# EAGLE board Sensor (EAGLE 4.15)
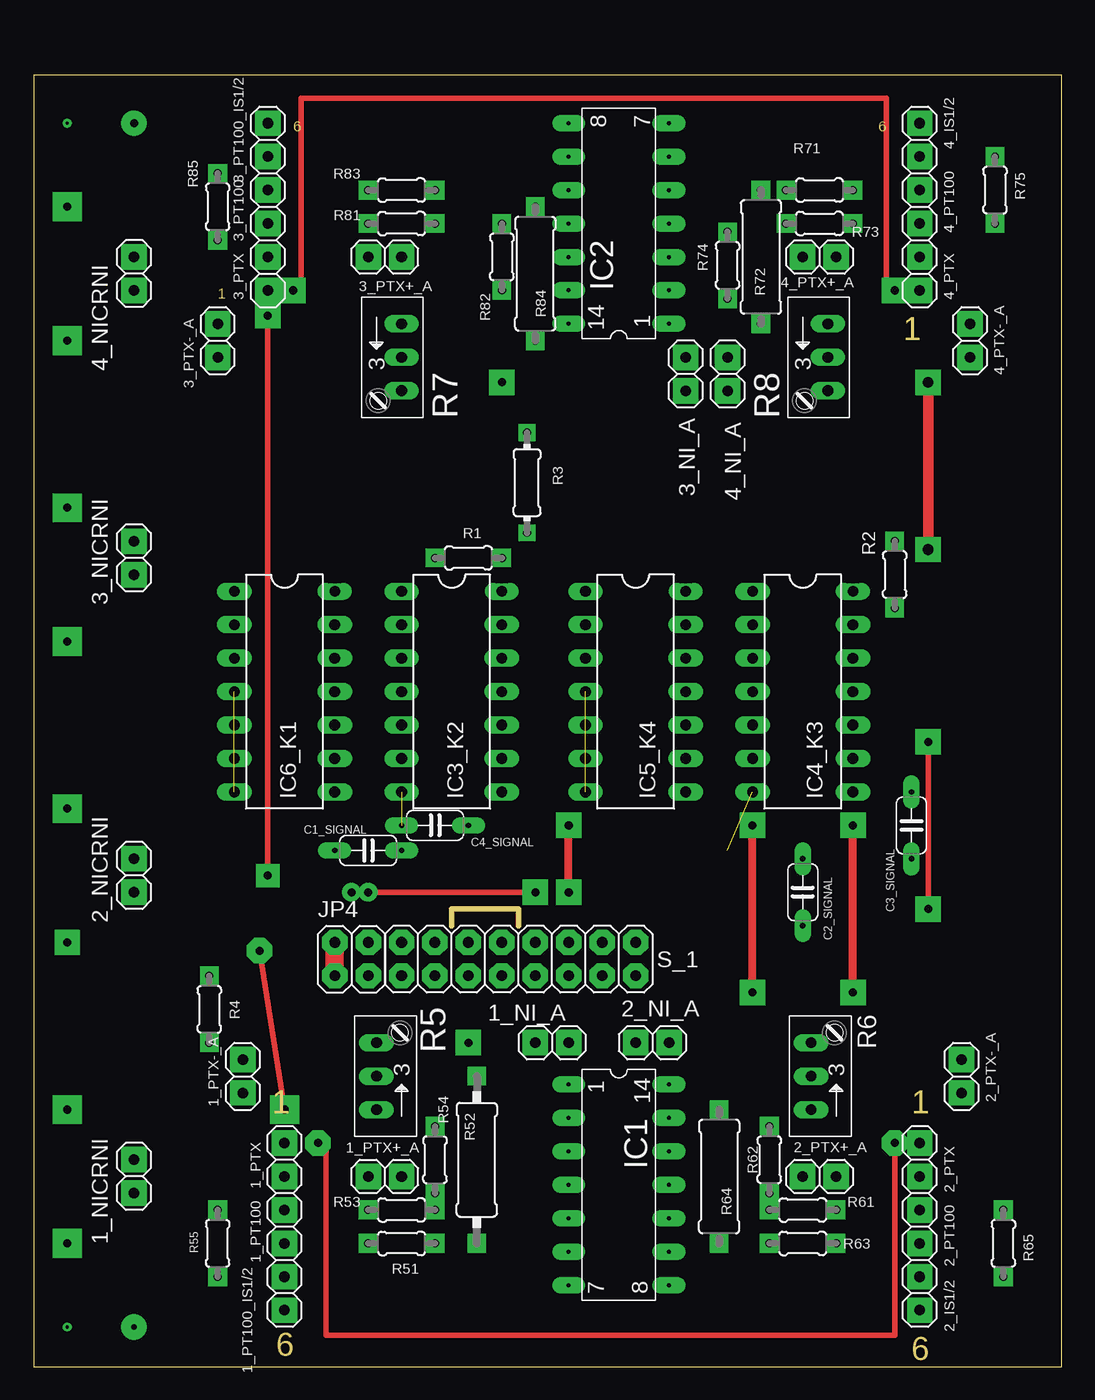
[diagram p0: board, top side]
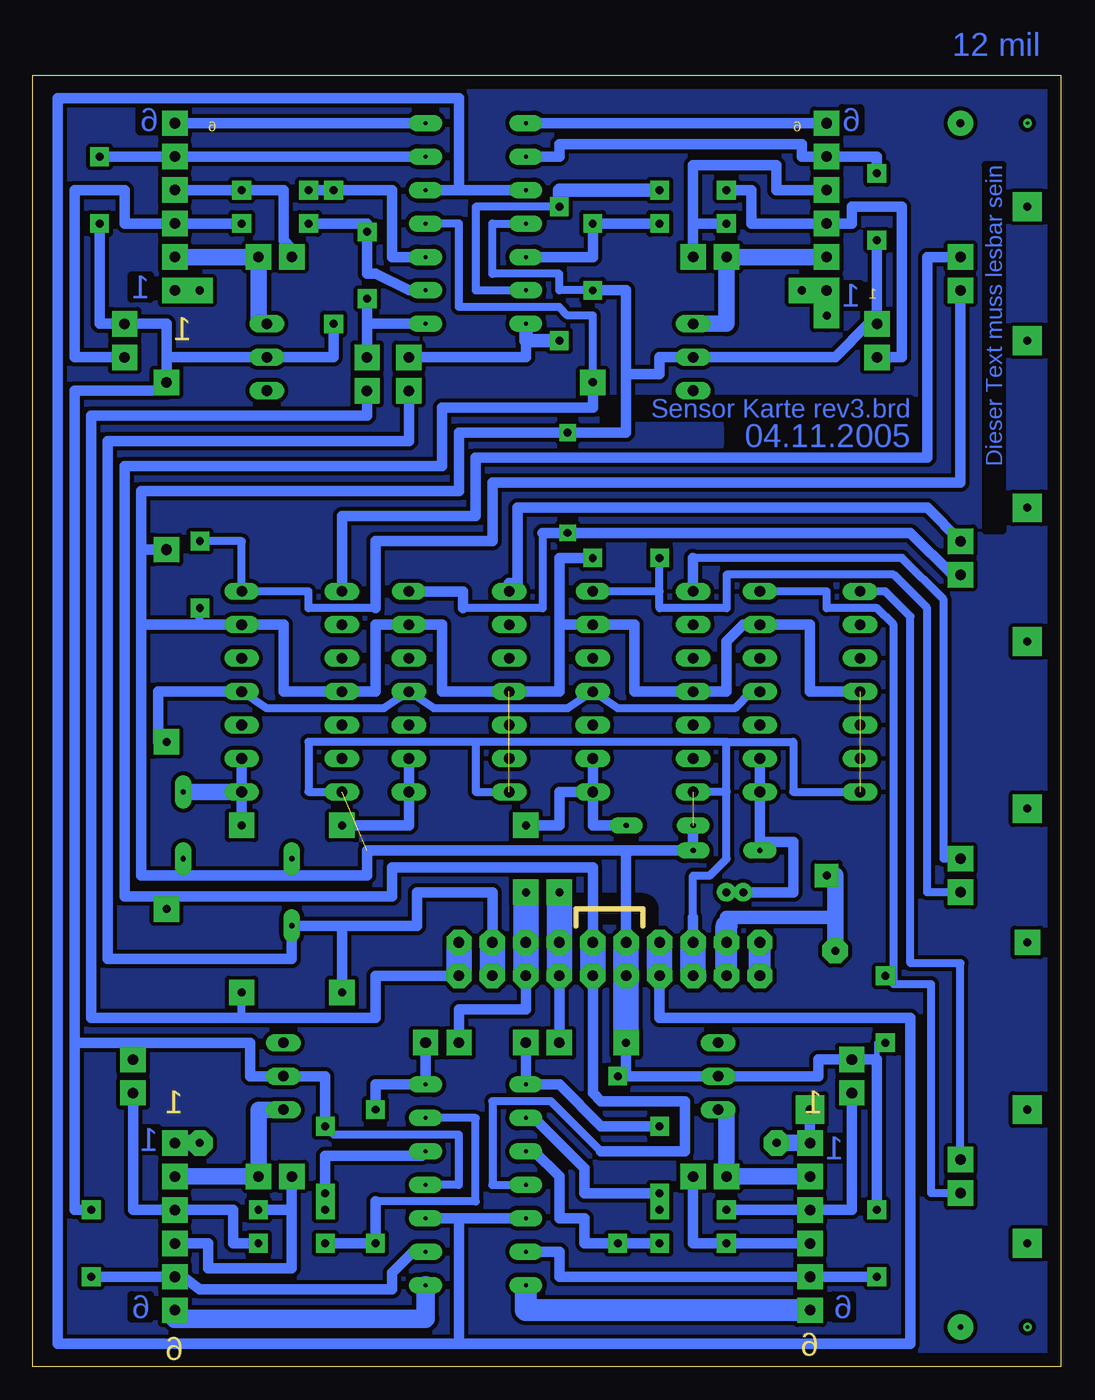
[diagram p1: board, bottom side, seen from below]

Size 78.09 x 98.09 mm. Coordinates in mm from the lower left corner, seen from the top.
Outline: 31.75,33.49 31.75,34.76 36.82,34.76 36.82,33.49
Outline: 0,0 78.09,0 78.09,98.09 0,98.09 0,0
Copper layers (1*16): Top 0.035mm / dielectric 1.5mm / Bottom 0.035mm
Design rules "default": minimum track width 10mil, minimum drill 24mil, track to track 12mil, track to pad 15mil, pad to pad 8mil, via to via 8mil, smd to smd 8mil, copper to edge 40mil, drill to drill 8mil, minimum pad ring 10mil, minimum via ring 8mil, stop-mask expansion 0mil, vias tented up to drill 0mil, thermal gap 10mil

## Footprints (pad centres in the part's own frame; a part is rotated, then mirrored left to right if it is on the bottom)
1X02 = drill 0.8 pad 1.93 square: 1 -1.27,0; 2 1.27,0
C050-024X044@1 = drill 0.406 pad 1.27 long: 1 -2.54,0; 2 2.54,0
DIL14@1 = drill 0.305 pad 1.27 long: 1 -7.62,-3.81; 2 -5.08,-3.81; 3 -2.54,-3.81; 4 0,-3.81; 5 2.54,-3.81; 6 5.08,-3.81; 7 7.62,-3.81; 8 7.62,3.81; 9 5.08,3.81; 10 2.54,3.81; 11 0,3.81; 12 -2.54,3.81; 13 -5.08,3.81; 14 -7.62,3.81
DIL14 = drill 0.813 long: 1 -7.62,-3.81; 2 -5.08,-3.81; 3 -2.54,-3.81; 4 0,-3.81; 5 2.54,-3.81; 6 5.08,-3.81; 7 7.62,-3.81; 8 7.62,3.81; 9 5.08,3.81; 10 2.54,3.81; 11 0,3.81; 12 -2.54,3.81; 13 -5.08,3.81 | drill 0.8 long: 14 -7.62,3.81
2X02 = drill 0.8 pad 1.93 octagon: 1 -1.27,-1.27; 2 -1.27,1.27; 3 1.27,-1.27; 4 1.27,1.27
0204/5 = drill 0.6 pad 1.422 square: 1 -2.54,0; 2 2.54,0
0204/7 = drill 0.6 pad 1.27 square: 1 -3.81,0; 2 3.81,0
RJ9W = drill 0.813 long: 1 2.54,0.635; 2 0,0.635; 3 -2.54,0.635
0309/12 = drill 0.6 pad 1.422 square: 1 -6.35,0; 2 6.35,0
0309/10 = drill 0.6 pad 1.422 square: 1 -5.08,0; 2 5.08,0
2X08 = drill 0.8 pad 1.93 octagon: 1 -8.89,-1.27; 2 -8.89,1.27; 3 -6.35,-1.27; 4 -6.35,1.27; 5 -3.81,-1.27; 6 -3.81,1.27; 7 -1.27,-1.27; 8 -1.27,1.27; 9 1.27,-1.27; 10 1.27,1.27; 11 3.81,-1.27; 12 3.81,1.27; 13 6.35,-1.27; 14 6.35,1.27; 15 8.89,-1.27; 16 8.89,1.27

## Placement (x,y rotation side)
1_NI_A  [1X02]  46.98,24.6 0 top
1_NICRNI  [1X02]  7.62,14.44 270 top
1_PT100  [1X02]  19.05,10.63 270 top
1_PT100_IS1/2  [1X02]  19.05,5.55 270 top
1_PTX  [1X02]  19.05,15.71 270 top
1_PTX+_A  [1X02]  26.67,14.44 180 top
1_PTX-_A  [1X02]  15.87,22.06 90 top
2_IS1/2  [1X02]  67.31,5.55 270 top
2_NI_A  [1X02]  52.7,75.4 270 top
2_NICRNI  [1X02]  7.62,37.3 270 top
2_PT100  [1X02]  67.31,10.63 270 top
2_PTX  [1X02]  67.31,15.71 270 top
2_PTX+_A  [1X02]  59.68,14.44 0 top
2_PTX-_A  [1X02]  70.48,22.06 90 top
3_NI_A  [1X02]  49.52,75.4 270 top
3_NICRNI  [1X02]  7.62,83.02 270 top
3_PT100  [1X02]  67.31,88.1 90 top
3_PT100_IS1/2  [1X02]  67.31,93.18 90 top
3_PTX  [1X02]  67.31,83.02 90 top
3_PTX+_A  [1X02]  59.68,84.29 0 top
3_PTX-_A  [1X02]  71.12,77.94 90 top
4_IS1/2  [1X02]  17.78,93.18 90 top
4_NI_A  [1X02]  39.36,24.6 0 top
4_NICRNI  [1X02]  7.62,61.43 270 top
4_PT100  [1X02]  17.78,88.1 90 top
4_PTX  [1X02]  17.78,83.02 90 top
4_PTX+_A  [1X02]  26.67,84.29 180 top
4_PTX-_A  [1X02]  13.96,77.94 90 top
C1_SIGNAL  [C050-024X044@1]  25.39,39.2 0 top
C2_SIGNAL  [C050-024X044@1]  58.41,36.03 90 top
C3_SIGNAL  [C050-024X044@1]  66.67,41.11 270 top
C4_SIGNAL  [C050-024X044@1]  30.48,41.11 0 top
IC1  LM324N  [DIL14@1]  44.45,13.81 270 top
IC2  LM324N  [DIL14@1]  44.45,86.83 90 top
IC3_K2  AD595AQ  [DIL14]  31.75,51.27 270 top
IC4_K3  AD595AQ  [DIL14]  58.41,51.27 270 top
IC5_K4  AD595AQ  [DIL14]  45.71,51.27 270 top
IC6_K1  AD595AQ  [DIL14]  19.05,51.27 270 top
JP4  [2X02]  24.12,30.95 0 top
R1  10K  [0204/5]  33.02,61.43 0 top
R2  10K  [0204/5]  65.4,60.16 90 top
R3  10K  [0204/7]  37.46,67.14 270 top
R4  10K  [0204/5]  13.33,27.14 90 top
R5  300 R  [RJ9W]  26.67,22.06 90 top
R6  300 R  [RJ9W]  59.68,22.06 90 top
R7  300 R  [RJ9W]  27.3,76.67 270 top
R8  300 R  [RJ9W]  59.68,76.67 270 top
R51  47K/536K  [0204/5]  27.94,9.36 0 top
R52  470K  [0309/12]  33.65,15.71 270 top
R53  47K/536K  [0204/5]  27.94,11.9 180 top
R54  470K  [0204/5]  30.48,15.71 270 top
R55  3K3  [0204/5]  13.96,9.36 270 top
R61  47K/536K  [0204/5]  58.41,11.9 0 top
R62  470K  [0204/5]  55.88,15.71 90 top
R63  47K/536K  [0204/5]  58.41,9.36 0 top
R64  470K  [0309/10]  52.06,14.44 90 top
R65  3K3  [0204/5]  73.66,9.36 270 top
R71  47K/536K  [0204/5]  59.68,89.37 180 top
R72  470K  [0309/10]  55.24,84.29 90 top
R73  47K/536K  [0204/5]  59.68,86.83 180 top
R74  470K  [0204/5]  52.7,83.65 270 top
R75  3K3  [0204/5]  73.02,89.37 90 top
R81  47K/536K  [0204/5]  27.94,86.83 0 top
R82  470K  [0204/5]  35.55,84.29 90 top
R83  47K/536K  [0204/5]  27.94,89.37 0 top
R84  470K  [0309/10]  38.09,83.02 270 top
R85  3K3  [0204/5]  13.96,88.1 90 top
S_1  Verbindungskabel  [2X08]  36.82,30.95 180 top

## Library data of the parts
1_NI_A 1_NICRNI 1_PT100 1_PT100_IS1/2 1_PTX 1_PTX+_A 1_PTX-_A 2_IS1/2 2_NI_A 2_NICRNI 2_PT100 2_PTX 2_PTX+_A 2_PTX-_A 3_NI_A 3_NICRNI 3_PT100 3_PT100_IS1/2 3_PTX 3_PTX+_A 3_PTX-_A 4_IS1/2 4_NI_A 4_NICRNI 4_PT100 4_PTX 4_PTX+_A 4_PTX-_A JP4 S_1 = pinhead
C1_SIGNAL C2_SIGNAL C3_SIGNAL C4_SIGNAL R1-R4 R51-R55 R61-R65 R71-R75 R81-R85 = rcl
IC1 IC2 = linear
IC3_K2 IC4_K3 IC5_K4 IC6_K1 = analog-devices
R5-R8 = pot

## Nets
+18V: 1_PTX.1 2_PTX.1 3_PTX.1 4_PTX.1 JP4.3
-5V: S_1.15 S_1.16
COM: 1_PTX-_A.2 2_PTX-_A.2 3_PTX-_A.2 4_PTX-_A.2 C1_SIGNAL.2 C2_SIGNAL.2 C3_SIGNAL.2 C4_SIGNAL.1 IC1.11 IC2.11 IC3_K2.4 IC3_K2.7 IC4_K3.4 IC4_K3.7 IC5_K4.4 IC5_K4.7 IC6_K1.4 IC6_K1.7 R1.2 R2.1 R3.1 R4.1 R5.2 R6.2 R7.2 R8.2 R52.1 R55.1 R62.2 R65.1 R72.1 R75.1 R82.1 R85.1 S_1.11 S_1.12
N$1: IC1.2 R53.1 R54.2
N$2: 1_PT100.1 1_PTX-_A.1 R53.2
N$3: IC1.3 R51.2 R52.2
N$4: 1_PT100.2 1_PTX+_A.1 R51.1
N$5: 2_IS1/2.2 IC1.8
N$6: IC1.13 R63.1 R64.1
N$7: 2_IS1/2.1 IC1.9 R65.2
N$8: 2_NICRNI.1 IC3_K2.1
N$9: 1_PTX+_A.2 1_PTX.2 R5.3
N$11: 1_PT100_IS1/2.2 IC1.7
N$12: IC1.5 IC1.10 IC2.5 IC2.10 S_1.13 S_1.14
N$13: 2_NI_A.2 C3_SIGNAL.1 IC4_K3.8 IC4_K3.9 S_1.1 S_1.2
N$14: 1_NI_A.1 C4_SIGNAL.2 IC3_K2.8 IC3_K2.9 S_1.5 S_1.6
N$15: 4_NI_A.1 C1_SIGNAL.1 IC6_K1.8 IC6_K1.9 S_1.7 S_1.8
N$16: 1_PT100_IS1/2.1 IC1.6 R55.2
N$17: IC1.12 R61.1 R62.1
N$18: IC2.3 R71.2 R72.2
N$19: 2_PT100.1 2_PTX-_A.1 R63.2
N$20: 2_PT100.2 2_PTX+_A.1 R61.2
N$21: 3_PT100_IS1/2.2 IC2.7
N$24: 3_PT100.1 3_PTX-_A.1 R73.1
N$25: 3_PT100.2 3_PTX+_A.1 R71.1
N$26: IC2.2 R73.2 R74.1
N$27: 3_PT100_IS1/2.1 IC2.6 R75.2
N$28: 4_PT100.2 4_PTX+_A.1 R81.1
N$29: 4_PT100.1 4_PTX-_A.1 R83.1
N$30: IC2.13 R83.2 R84.1
N$31: IC2.12 R81.2 R82.2
N$32: 3_NICRNI.2 IC4_K3.14 R2.2
N$33: 3_NI_A.2 C2_SIGNAL.1 IC5_K4.8 IC5_K4.9 S_1.3 S_1.4
N$34: 4_IS1/2.2 IC2.8
N$35: 4_IS1/2.1 IC2.9 R85.2
N$36: 3_NICRNI.1 IC4_K3.1
N$38: 4_NICRNI.2 IC5_K4.14 R3.2
N$39: 4_NICRNI.1 IC5_K4.1
N$40: 1_NICRNI.2 IC6_K1.14 R4.2
N$41: 1_NICRNI.1 IC6_K1.1
N$42: IC6_K1.13
N$43: IC5_K4.13
N$44: IC4_K3.13
N$45: IC3_K2.13
N$59: 4_NI_A.2 IC1.1 R54.1
N$60: 2_NICRNI.2 IC3_K2.14 R1.1
N$61: 1_NI_A.2 IC1.14 R64.2
N$62: 3_NI_A.1 IC2.14 R84.2
N$63: 2_NI_A.1 IC2.1 R74.2
N$64: JP4.1 JP4.2
N$66: 2_PTX+_A.2 2_PTX.2 R6.3
N$70: 3_PTX+_A.2 3_PTX.2 R8.3
N$73: 4_PTX+_A.2 4_PTX.2 R7.3
V+: IC1.4 IC2.4 IC3_K2.11 IC4_K3.11 IC5_K4.11 IC6_K1.11 S_1.9 S_1.10

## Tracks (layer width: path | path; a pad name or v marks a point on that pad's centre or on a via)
+18V  (via drill 0.61, 0.61 pad 1.78, 0.61 pad 1.93)  (1 unrouted)
  Top 0.406: v21.59,16.98 22.22,16.98 22.22,2.38 65.4,2.38 v65.4,16.98 | v19.05,19.52 v17.14,31.59 | v17.78,37.3 v17.78,79.84 | v19.68,81.75 20.32,81.75 20.32,96.35 64.77,96.35 64.77,81.75 65.4,81.75
  Bottom 0.813: 1_PTX.1 v19.05,19.52
  Bottom 1.016: v17.14,31.59 17.14,34.12 25.39,34.12 JP4.3
  Bottom 1.27: 1_PTX.1 v21.59,16.98 | v65.4,16.98 2_PTX.1 | v17.14,31.59 17.14,35.4 17.14,37.3 v17.78,37.3
  Bottom 1.676: JP4.3 25.39,33.49
  Bottom 1.93: v19.68,81.75 4_PTX.1 v17.78,79.84 | 65.4,81.75 3_PTX.1
-5V
  Bottom 0.61: 15.23,43.65 20.32,43.65 20.32,47.46 25.39,47.46 | 25.39,43.65 25.39,47.46 | 25.39,47.46 44.45,47.46 | 41.9,43.65 44.45,43.65 44.45,47.46 | 44.45,47.46 57.14,47.46 57.14,43.65 54.6,43.65 | S_1.16 27.94,30.32 | 25.39,43.65 27.94,43.65 | 25.39,43.65 25.39,38.57 26.67,37.3 27.94,37.3 S_1.15
  Bottom 0.813: 27.3,29.68 S_1.15 27.94,34.12
  Bottom 1.93: S_1.16 S_1.15
COM  (via drill 0.61 pad 1.93, 0.81 pad 1.93)  (4 unrouted)
  Top 0.813: v67.94,62.06 v67.94,74.77
  Bottom 0.406: IC6_K1.4 17.78,51.27 | 55.24,17.62 R62.2 | 58.41,37.3 C2_SIGNAL.2 | R4.1 13.96,24.6 13.96,22.7
  Bottom 0.61: IC3_K2.4 26.67,51.27 | 40.63,51.27 IC5_K4.4 43.17,51.27 | IC2.11 43.17,86.83 43.17,83.02 38.09,83.02 38.09,81.75 R82.1 | IC4_K3.4 53.34,51.27 | 65.4,56.35 R2.1 | IC1.11 45.71,13.81 45.71,17.62 55.24,17.62 | R55.1 13.96,16.98
  Bottom 0.813: IC6_K1.4 19.05,51.27 19.05,56.35 24.12,56.35 25.39,55.08 25.39,51.27 26.67,51.27 | R1.2 38.09,61.43 38.09,56.35 | IC3_K2.4 32.38,51.27 32.38,56.35 38.09,56.35 | 38.09,56.35 38.09,51.27 40.63,51.27 | 43.17,51.27 46.98,51.27 46.98,56.35 52.06,56.35 52.06,51.27 53.34,51.27 | IC4_K3.4 59.05,51.27 59.05,56.35 65.4,56.35 69.84,56.35 | R82.1 33.02,81.75 33.02,75.4 | 69.84,66.51 45.71,66.51 45.71,70.95 R3.1 33.02,70.95 33.02,75.4 | R65.1 74.93,11.9 74.93,24.6 | 74.93,24.6 74.93,74.13 67.94,74.13 v67.94,74.77 67.94,76.67 | 69.84,37.3 69.84,56.35 | 69.84,56.35 69.84,66.51 | 69.84,37.3 58.41,37.3 52.7,37.3 52.7,39.2 33.02,39.2 | 70.48,24.6 74.93,24.6 | R62.2 55.88,22.06 R6.2 61.59,22.06 61.59,24.6 70.48,24.6 | 70.48,24.6 2_PTX-_A.2 | S_1.11 33.02,39.2 | 33.02,22.06 R52.1 | 33.02,22.06 v33.02,24.6 | R55.1 13.96,22.7 13.96,23.33 1_PTX-_A.2 18.41,23.33 18.41,22.06 R5.2 33.02,22.06 | 69.84,37.3 66.67,37.3 C3_SIGNAL.2 | 33.02,39.2 C1_SIGNAL.2 C4_SIGNAL.1 | 69.84,66.51 69.84,62.06 v67.94,62.06 | R85.1 4_PTX-_A.2 14.6,79.21 17.14,76.67 R7.2 30.48,76.67 30.48,75.4 33.02,75.4 | R72.1 55.24,76.67 R8.2 67.94,76.67 | 67.94,76.67 67.94,79.21 3_PTX-_A.2 73.02,79.21 R75.1
  Bottom 1.93: S_1.11 S_1.12 v33.02,24.6
N$1
  Bottom 0.813: R53.1 R54.2 36.19,13.17 36.19,15.08 40,18.89 IC1.2
N$2
  Bottom 0.813: 1_PTX-_A.1 15.87,11.9 1_PT100.1 R53.2
N$3
  Bottom 0.813: R51.2 R52.2 36.19,9.36 36.19,11.27 38.09,11.27 38.09,14.44 40,16.35 IC1.3
N$4
  Bottom 0.813: 1_PT100.2 R51.1 27.94,9.36 1_PTX+_A.1
N$5
  Bottom 1.422: IC1.8 48.25,3.65 67.31,3.65 2_IS1/2.2
N$6
  Bottom 0.61: IC1.13 44.45,18.89 44.45,12.54 52.06,12.54
  Bottom 0.813: 52.06,12.54 R64.1 R63.1
N$7
  Bottom 0.813: R65.2 2_IS1/2.1 66.67,6.82 65.4,5.87 50.79,5.87 50.79,7.14 49.21,8.73 IC1.9
N$8
  Bottom 0.61: 27.94,61.43 12.06,61.43 8.88,58.26 8.88,38.57 2_NICRNI.1
  Bottom 0.813: 27.94,61.43 IC3_K2.1
N$9
  Bottom 1.27: R5.3 25.39,19.52 1_PTX+_A.2 1_PTX.2
N$11
  Bottom 0.813: 40.63,5.87 IC1.7
  Bottom 1.676: 1_PT100_IS1/2.2 39.36,4.28 40.63,4.28 40.63,5.87
N$12
  Bottom 0.406: 45.71,89.37 IC2.5
  Bottom 0.813: S_1.14 30.48,26.51 11.42,26.51 11.42,1.74 45.71,1.74 | 45.72,1.74 76.2,1.74 76.2,96.35 45.71,96.35 45.71,89.37 | 45.71,1.74 45.72,1.74 | 45.72,1.74 45.71,3.65 | 45.71,1.74 45.71,3.65 | 45.71,3.65 45.71,11.27 | 45.71,11.27 IC1.5 | 45.71,11.27 IC1.10 | IC2.5 IC2.10
  Bottom 1.93: S_1.14 S_1.13
N$13  (via drill 0.61 pad 1.93)
  Top 0.61: v62.22,28.41 v62.22,41.11
  Bottom 0.61: S_1.2 S_1.1 | 62.22,26.51 v62.22,28.41
  Bottom 0.813: S_1.2 52.06,29.68 52.06,26.51 62.22,26.51 73.66,26.51 73.66,72.22 52.7,72.22 2_NI_A.2 | IC4_K3.9 IC4_K3.8 v62.22,41.11
  Bottom 1.27: IC4_K3.8 C3_SIGNAL.1
  Bottom 1.93: S_1.2 S_1.1
N$14  (via drill 0.61 pad 1.93)
  Top 0.61: v40.63,36.03 v40.63,41.11
  Bottom 0.406: S_1.6 40,30.95
  Bottom 0.813: IC3_K2.8 IC3_K2.9 | IC3_K2.8 38.09,43.65 38.09,41.11 v40.63,41.11 | S_1.6 40.63,27.14 45.71,27.14 1_NI_A.1 | IC3_K2.8 35.55,41.11 C4_SIGNAL.2
  Bottom 1.93: S_1.6 S_1.5 v40.63,36.03
N$15  (via drill 0.61 pad 1.42, 0.61 pad 1.93)
  Top 0.406: v25.39,36.03 v38.09,36.03
  Bottom 0.813: IC6_K1.9 IC6_K1.8 22.86,39.84 | v25.39,36.03 20.32,36.03 20.32,39.84 22.86,39.84 | 22.86,39.84 C1_SIGNAL.1 | S_1.8 4_NI_A.1
  Bottom 1.93: S_1.8 S_1.7 v38.09,36.03
N$16
  Bottom 0.813: R55.2 1_PT100_IS1/2.1 38.09,6.82 38.09,8.73 IC1.6
N$17
  Bottom 0.813: R61.1 R62.1 55.88,16.03 50.48,16.03 48.57,16.03 IC1.12
N$18
  Bottom 0.813: R71.2 R72.2 50.79,89.37 50.79,84.29 IC2.3
N$19
  Bottom 0.813: R63.2 62.86,9.36 62.86,11.9 2_PT100.1 70.48,11.9 2_PTX-_A.1
N$20
  Bottom 0.813: 58.41,11.9 R61.2 | 58.41,11.9 58.41,7.46 64.77,7.46 64.77,9.36 2_PT100.2 | 58.41,11.9 2_PTX+_A.1
N$21
  Bottom 0.813: IC2.7 3_PT100_IS1/2.2
N$24
  Bottom 0.813: R73.1 3_PT100.1 71.12,86.83 71.12,89.37 74.93,89.37 74.93,76.67 3_PTX-_A.1
N$25
  Bottom 0.813: 3_PT100.2 R71.1 59.05,89.37 59.05,85.56 58.41,84.92 3_PTX+_A.1
N$26
  Bottom 0.813: IC2.2 49.52,81.75 52.06,83.02 52.7,83.02 R74.1 52.7,86.83 R73.2
N$27
  Bottom 0.61: 72.39,91.91 R75.2
  Bottom 0.813: 72.39,91.91 3_PT100_IS1/2.1 IC2.6
N$28
  Bottom 0.813: 27.94,86.83 4_PTX+_A.1 | 27.94,86.83 R81.1 | 4_PT100.2 21.59,89.37 21.59,91.27 27.94,91.27 27.94,86.83
N$29
  Bottom 0.813: R83.1 23.49,89.37 23.49,86.83 4_PT100.1 15.87,86.83 15.87,88.1 12.06,88.1 12.06,76.67 4_PTX-_A.1
N$30
  Bottom 0.61: R84.1 44.45,88.1 44.45,81.75 IC2.13
  Bottom 1.016: R83.2 38.09,89.37 R84.1
N$31
  Bottom 0.813: R81.2 R82.2 35.55,84.29 IC2.12
N$32
  Bottom 0.61: 52.06,57.62 57.14,57.62 57.14,58.89 IC4_K3.14 62.22,62.7 R2.2
  Bottom 0.813: 52.06,57.62 52.06,62.7 43.17,62.7 43.17,67.14 7.62,67.14 3_NICRNI.2
N$33  (via drill 0.61 pad 1.93)
  Top 0.61: v54.6,28.41 v54.6,41.11
  Bottom 0.813: S_1.3 43.17,36.03 48.89,36.03 48.89,33.49 54.6,33.49 | IC5_K4.9 IC5_K4.8 49.52,41.11 v54.6,41.11 | 54.6,29.05 v54.6,28.41 54.6,33.49 | 54.6,33.49 C2_SIGNAL.1 58.41,30.95 72.39,30.95 72.39,70.32 49.52,70.32 3_NI_A.2
  Bottom 1.93: S_1.4 S_1.3
N$34
  Bottom 0.813: 4_IS1/2.2 IC2.8
N$35
  Bottom 0.813: R85.2 13.96,91.91 4_IS1/2.1 19.68,91.91 19.68,92.86 38.09,92.86 38.09,91.91 IC2.9
N$36
  Bottom 0.813: IC4_K3.1 54.6,64.6 44.45,64.6 44.45,69.05 10.15,69.05 10.15,84.29 3_NICRNI.1
N$38
  Bottom 0.61: 45.4,57.62 39.36,57.62 39.36,63.34
  Bottom 0.813: IC5_K4.14 45.4,58.89 45.4,57.62 | 39.36,63.34 R3.2 11.42,63.34 8.25,60.16 4_NICRNI.2
N$39
  Bottom 0.61: 41.9,59.52 IC5_K4.1
  Bottom 0.813: 41.9,59.52 41.27,59.52 41.27,65.24 10.15,65.24 4_NICRNI.1
N$40
  Bottom 0.406: R4.2 12.69,29.68 12.69,31.59
  Bottom 0.61: IC6_K1.14 17.78,58.89 17.78,57.62 13.96,57.62 12.69,56.35 12.69,31.59 12.69,29.05 9.84,29.05 9.84,13.17 1_NICRNI.2
N$41
  Bottom 0.61: IC6_K1.1 13.33,58.89 11.42,56.98 11.42,30.63 7.62,30.63 1_NICRNI.1
N$46  (via drill 0.25 pad 0.25)
  other vias: 2.54,94.45
N$47  (via drill 0.61 pad 1.93)
  other vias: 7.62,94.45
N$48  (via drill 0.41 pad 1.93)
  other vias: 7.62,3.01
N$49  (via drill 0.25 pad 0.25)
  other vias: 2.54,3.01
N$50
  pour Bottom: 0.63,98.26 -0.01,98.26 -0.01,-0.17 78.1,-0.17 78.1,98.26 -0.01,98.26
N$51  (via drill 0.61 pad 2.18)
  other vias: 2.54,88.1
N$52  (via drill 0.61 pad 2.18)
  other vias: 2.54,77.94
N$53  (via drill 0.61 pad 2.18)
  other vias: 2.54,9.36
N$54  (via drill 0.61 pad 2.18)
  other vias: 2.54,19.52
N$55  (via drill 0.61 pad 2.18)
  other vias: 2.54,65.24
N$56  (via drill 0.61 pad 2.18)
  other vias: 2.54,55.08
N$57  (via drill 0.61 pad 2.18)
  other vias: 2.54,42.38
N$58  (via drill 0.61 pad 2.18)
  other vias: 19.05,19.52
N$59
  Bottom 0.813: R54.1 34.92,18.25 38.09,21.43 IC1.1 4_NI_A.2
N$60
  Bottom 0.61: 30.48,58.89 30.48,57.62 25.39,57.62 25.39,60.16 12.69,60.16 10.15,57.62 10.15,36.03 2_NICRNI.2 | 30.48,58.89 IC3_K2.14 | 30.48,58.89 R1.1
N$61
  Bottom 0.813: R64.2 52.06,21.43 IC1.14 1_NI_A.2
N$62
  Bottom 0.813: 3_NI_A.1 40.63,76.67 40.63,77.94
  Bottom 1.016: R84.2 40.63,77.94 IC2.14
N$63
  Bottom 0.813: IC2.1 52.7,79.21 R74.2 2_NI_A.1
N$64
  Top 1.422: JP4.2 JP4.1
  Bottom 1.676: JP4.1 JP4.2
N$65  (via drill 0.61 pad 1.93)
  other vias: 2.54,32.22
N$66
  Bottom 1.27: 2_PTX.2 2_PTX+_A.2 60.95,19.52 R6.3
N$67  (via drill 0.61 pad 1.93)
  other vias: 17.78,79.84
N$68  (via drill 0.61 pad 1.93)
  other vias: 19.68,81.75
N$69  (via drill 0.61 pad 1.93)
  other vias: 65.4,81.75
N$70
  Bottom 1.27: 3_PTX.2 3_PTX+_A.2 60.95,79.21 R8.3
N$71  (via drill 0.61 pad 1.93)
  other vias: 67.94,34.76
N$73
  Bottom 1.27: 4_PTX.2 4_PTX+_A.2 25.39,79.21 R7.3
N$74  (via drill 0.61 pad 1.42)
  other vias: 24.12,36.03
V+  (via drill 0.61 pad 1.93)  (1 unrouted)
  Top 0.406: v67.94,47.46 67.94,34.76
  Bottom 0.406: 67.94,35.71 67.94,34.76
  Bottom 0.61: IC6_K1.11 23.49,51.27 24.76,50 33.65,50 IC3_K2.11 37.46,50 47.62,50 IC5_K4.11 51.43,50 60.32,50 IC4_K3.11 | IC2.4 45.71,86.83 45.71,80.48 38.09,80.48 37.46,79.84 35.55,79.84 v35.55,74.77 | 34.92,16.35 38.73,20.16 43.17,20.16 43.17,13.81 IC1.4
  Bottom 0.813: S_1.9 35.55,37.94 50.79,37.94 50.79,35.71 67.94,35.71 71.12,35.71 71.12,68.41 46.98,68.41 46.98,72.86 35.55,72.86 v35.55,74.77 | IC4_K3.11 68.58,51.27 68.58,47.46 v67.94,47.46 | S_1.10 35.55,20.79 34.92,20.16 28.57,20.16 28.57,16.35 34.92,16.35
  Bottom 1.93: S_1.10 S_1.9

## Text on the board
Bottom: 12 mil | 6 | 6 | Dieser Text muss lesbar sein | 1 | 1 | Sensor Karte rev3.brd | 04.11.2005 | 1 | 1 | 6 | 6
Dimension: 6 | 6 | 1 | 1 | 1 | 1 | 6 | 6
